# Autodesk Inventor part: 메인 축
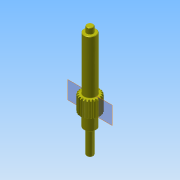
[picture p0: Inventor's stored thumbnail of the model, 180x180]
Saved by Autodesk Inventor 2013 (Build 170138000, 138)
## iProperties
Created: 2016-02
Part Number: 메인 축
Material: 강철, 연강
Document SubType Name: Modeling
Categories: <?xml version="1.0" encoding="UTF-16"?> <MemberInstance><Categories><FamilyTemplate><FamilyTemplateParameter ValueType="xs:double" Id="1" ObjectReferenceKey="da
Density: 7.86 g/cm^3
Mass: 187.503 g
Surface Area: 82.0529 cm^2
Volume: 23.8554 cm^3
Author: mdu
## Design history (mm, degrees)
sketch "Sketch1"
  geometry: C1 r 12 at (0, 0)
  constraints: 1 centre point
  dimensions: "d0" = 24 diameter of C1 (= da_da)
extrude "Extrusion1" new body sketch "Sketch1" distance "d1" = 20 (= da_b); taper "d2" = 0 deg
workplane "Work Plane2"
feature "피치 지름" dims "d4" = 10, "d5" = 0
workplane "Work Plane8"
workplane "Work Plane9"
chamfer "모따기1" distance "d49" = 1; stored, may be unused: second distance "d50" = 2, angle "d51" = 45 deg
sketch "스케치3"
  geometry: C1 r 7.5 at (0, 0); 1 further point
  constraints: 1 centre point, 1 coincident
  dimensions: "d52" = 15 diameter of C1
extrude "돌출2" join sketch "스케치3" distance "d53" = 66; taper "d54" = 0 deg
sketch "스케치4"
  geometry: C1 r 4 at (0, 0); 1 further point
  constraints: 1 centre point, 1 coincident
  dimensions: "d55" = 8 diameter of C1
extrude "돌출3" join sketch "스케치4" distance "d56" = 7; taper "d57" = 0 deg
sketch "스케치5"
  geometry: C1 r 7.5 at (0, 0) reference; C2 r 7.5 at (0, 0) reference; 1 further point
extrude "돌출4" join sketch "스케치5" distance "d62" = 16; taper "d63" = 0 deg
sketch "스케치6"
  geometry: C1 r 4 at (0, 0); 1 further point
  constraints: 1 centre point, 1 coincident
  dimensions: "d64" = 8 diameter of C1
extrude "돌출5" join sketch "스케치6" distance "d65" = 30; taper "d66" = 0 deg
chamfer "모따기2" distance "d58" = 0.5; stored, may be unused: second distance "d59" = 2, angle "d60" = 45 deg
fillet "모깎기1" dims "d61" = 0.5
feature "스퍼 기어" dims "da_b" = 20, "da_d" = 22, "da_aw" = 31, "da_da" = 24, "da_df" = 19.5, "da_dw" = 22, angle "da_beta" = 0 deg, "da_lefttooth" = 0, "da_righttooth" = 0
sketch "스케치7" dims "d68" = 18
  geometry: C1 r 0.25 at (0, -9); 2 further points
  constraints: 2 vertical alignment, 1 centre point, 1 coincident, 2 other
  dimensions: "d67" = 0.5 diameter of C1
extrude "돌출6" join sketch "스케치7" distance "d69" = 0.3; taper "d70" = 0 deg
body "Solid1"
sketch "Sketch2"
  geometry: C1 r 12 at (0, 0) reference; C2 r 11 at (0, 0)
  constraints: 1 centre point, 1 coincident
  dimensions: "d3" = 22 diameter of C2 (= da_dw)
body "Srf1"
node "투영된 루프1"
other parameters: "d16" = 31 (= da_aw), "d17" = 0, "d34" = 1.428 (computed from da_z), "d39" = 0, "d41" = 0, "d43" = 31 (= da_aw), "d46" = 31 (= da_aw), "d47" = 0, "d48" = 0
